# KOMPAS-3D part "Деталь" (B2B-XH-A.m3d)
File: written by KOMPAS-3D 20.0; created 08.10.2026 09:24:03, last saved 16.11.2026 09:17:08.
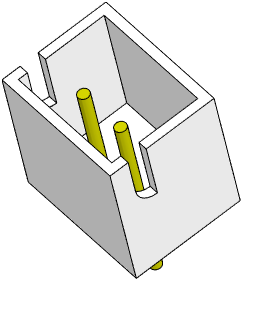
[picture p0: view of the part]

Document properties: Полное имя файла: D:\RicWork\Project-EPS32\box_compas\разъемы\B2B-XH-A.m3d

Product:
- Part/product: Деталь
    Масса: 0.000922909

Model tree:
1. Эскиз:1
2. Элемент выдавливания:1
     Расстояние 1 = 7
3. Эскиз:2  (with: Элемент выдавливания:1)
4. Эскиз:3  (with: Элемент выдавливания:1)
5. Элемент выдавливания:3
     Расстояние 2 = 7.4
6. Скругление:1  (with: Элемент выдавливания:3)
     Радиус = 1
7. Эскиз:4  (with: Элемент выдавливания:1)
8. Элемент выдавливания:4
     Расстояние 1 = 3.4
9. Массив по сетке:1  (with: Элемент выдавливания:4, Эскиз:4)  (2 pattern instances)
     Шаг 1 = 10; Угол раствора = -90; Шаг 2 = 2.54
10. Элемент выдавливания:6
     Расстояние 2 = 6
11. Эскиз:6  (with: Элемент выдавливания:6, Элемент выдавливания:1)
12. Элемент выдавливания:7
     Расстояние 1 = 5
13. Массив по сетке:2  (with: Элемент выдавливания:7, Эскиз:6)  (2 pattern instances)
     Шаг 1 = 10; Угол раствора = 90; Шаг 2 = 2.54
